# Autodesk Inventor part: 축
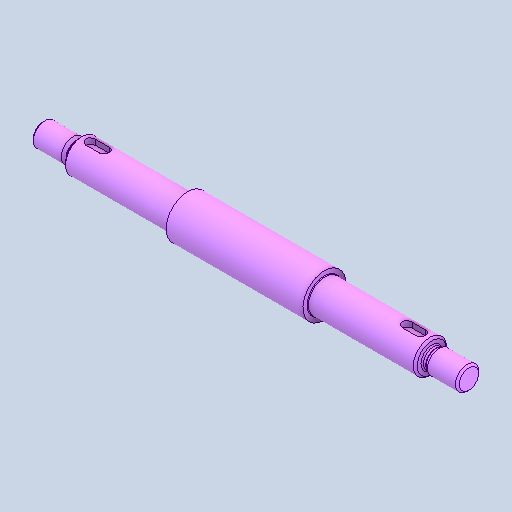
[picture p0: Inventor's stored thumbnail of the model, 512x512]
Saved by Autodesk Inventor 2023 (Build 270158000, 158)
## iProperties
Created: 2025-03
Part Number: 축
Material: 강철, 탄소
Document SubType Name: Modeling
Designer: user
Density: 7.85 g/cm^3
Appearance: 기본값
Author: jhkim
Sending System: Autodesk Inventor 2025
Preprocessor: ST-DEVELOPER v20
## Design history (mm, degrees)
feature "솔리드1"
node "솔리드2"
